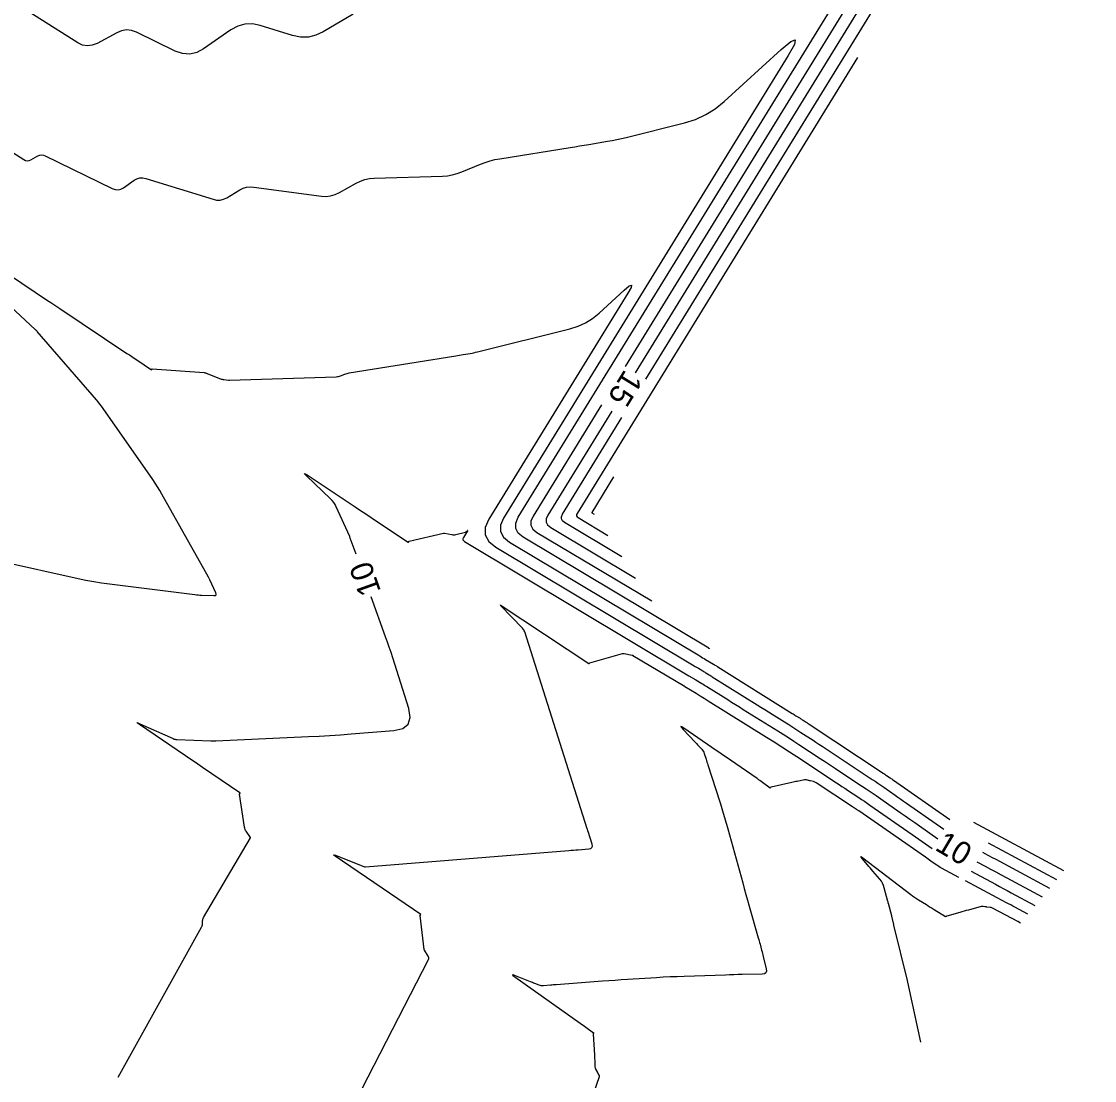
# Model space of a CAD drawing. Extents: x 1797789 to 1803805, y 249066 to 250293.
# Drawn here: x 1798416.4 to 1798702, y 249648.7 to 249930.5 of the extents above; entities that cross this region are included whole.
import ezdxf

# ---------------------------------------------------------------- set-up
doc = ezdxf.new("R2010")
doc.units = 0
doc.layers.add('33', color=7, linetype='Continuous')
doc.layers.add('34', color=7, linetype='Continuous')

msp = doc.modelspace()

# ---------------------------------------------------------------- linework, layer by layer
at = {"layer": '33'}
for points in [[(1798699.28, 250031.22), (1798579.8, 249837.04)], [(1798573.51, 249826.82), (1798556.48, 249799.14), (1798556.07, 249798.17), (1798556.06, 249797.31), (1798556.46, 249796.55), (1798557.28, 249795.89), (1798579.84, 249782.4)], [(1798505.48, 249788.76), (1798503.94, 249793.08), (1798503.9, 249793.17), (1798503.86, 249793.27), (1798503.82, 249793.37), (1798503.78, 249793.46), (1798500.21, 249801.39), (1798499.91, 249801.97), (1798499.56, 249802.52), (1798499.16, 249803.03), (1798498.71, 249803.5), (1798492.25, 249809.64), (1798491.81, 249810.08), (1798491.7, 249810.27), (1798491.9, 249810.19), (1798492.43, 249809.86), (1798505.2, 249801.37), (1798506.62, 249800.43), (1798508.04, 249799.49), (1798509.46, 249798.54), (1798510.88, 249797.6), (1798519.38, 249791.96), (1798519.39, 249791.96), (1798519.41, 249791.95), (1798519.42, 249791.96), (1798519.43, 249791.97), (1798519.59, 249792.21), (1798519.59, 249792.22), (1798519.6, 249792.21), (1798519.6, 249792.21), (1798528.76, 249794.39), (1798528.82, 249794.4), (1798528.88, 249794.41), (1798528.93, 249794.4), (1798528.99, 249794.39), (1798530.94, 249793.99), (1798531.21, 249793.95), (1798531.48, 249793.94), (1798531.75, 249793.96), (1798532.01, 249794.01), (1798534.57, 249794.65), (1798534.65, 249794.67), (1798534.73, 249794.71), (1798534.8, 249794.75), (1798534.86, 249794.8), (1798535.11, 249795.03), (1798535.16, 249795.08), (1798535.19, 249795.08), (1798535.18, 249795.06), (1798535.15, 249795), (1798534.05, 249793.21), (1798533.91, 249792.9), (1798533.91, 249792.63), (1798534.04, 249792.39), (1798534.3, 249792.18), (1798594.06, 249756.45), (1798594.22, 249756.36), (1798594.37, 249756.27), (1798594.52, 249756.18), (1798594.67, 249756.09), (1798595.27, 249755.72), (1798595.42, 249755.63), (1798595.57, 249755.54), (1798595.72, 249755.45), (1798595.87, 249755.36), (1798597.53, 249754.35), (1798597.86, 249754.16), (1798598.19, 249753.96), (1798598.51, 249753.76), (1798598.84, 249753.55), (1798604.39, 249750.09), (1798605.42, 249749.44), (1798606.45, 249748.79), (1798607.49, 249748.15), (1798608.52, 249747.5), (1798617.71, 249741.77), (1798619.13, 249740.88), (1798620.54, 249739.98), (1798621.95, 249739.07), (1798623.35, 249738.15), (1798629.03, 249734.4), (1798630.39, 249733.51), (1798631.74, 249732.61), (1798633.1, 249731.72), (1798634.45, 249730.83), (1798639.97, 249727.18), (1798641.27, 249726.32), (1798642.57, 249725.44), (1798643.86, 249724.56), (1798645.15, 249723.67), (1798650.3, 249720.09), (1798651.58, 249719.2), (1798652.87, 249718.3), (1798654.15, 249717.41), (1798655.44, 249716.51), (1798660.35, 249713.08)], [(1798442.18, 249649.63), (1798464.36, 249689.51), (1798464.46, 249689.71), (1798464.53, 249689.92), (1798464.58, 249690.13), (1798464.6, 249690.36), (1798464.63, 249691.25), (1798464.66, 249691.48), (1798464.7, 249691.69), (1798464.78, 249691.89), (1798464.88, 249692.09), (1798477.37, 249713.28), (1798477.39, 249713.31), (1798477.39, 249713.34), (1798477.39, 249713.37), (1798477.37, 249713.4), (1798476.25, 249715.05), (1798476.1, 249715.31), (1798475.98, 249715.57), (1798475.89, 249715.85), (1798475.83, 249716.13), (1798474.45, 249724.96), (1798474.45, 249724.97), (1798474.44, 249724.97), (1798474.45, 249724.97), (1798474.6, 249725.21), (1798474.61, 249725.23), (1798474.61, 249725.24), (1798474.61, 249725.26), (1798474.59, 249725.27), (1798464.61, 249732.05), (1798463.97, 249732.48), (1798463.34, 249732.91), (1798462.71, 249733.34), (1798462.08, 249733.77), (1798447.83, 249743.43), (1798447.32, 249743.8), (1798447.18, 249743.96), (1798447.39, 249743.92), (1798447.97, 249743.68), (1798456.82, 249739.71), (1798457.06, 249739.61), (1798457.31, 249739.54), (1798457.56, 249739.49), (1798457.82, 249739.47), (1798466.86, 249739.15), (1798467.18, 249739.14), (1798467.51, 249739.14), (1798467.84, 249739.15), (1798468.17, 249739.16), (1798492.86, 249740.25), (1798495.7, 249740.39), (1798498.54, 249740.55), (1798501.38, 249740.74), (1798504.22, 249740.96), (1798515.56, 249741.88), (1798517.93, 249742.42), (1798519.38, 249743.58), (1798519.91, 249745.36), (1798519.51, 249747.76), (1798515.23, 249761.23), (1798514.78, 249762.63), (1798514.32, 249764.02), (1798513.84, 249765.41), (1798513.35, 249766.79), (1798509.53, 249777.46)], [(1798670.67, 249706.95), (1798672.89, 249705.77), (1798674.33, 249705), (1798675.76, 249704.24), (1798677.2, 249703.47), (1798678.63, 249702.7), (1798688.06, 249697.65)]]:
    msp.add_lwpolyline(points, dxfattribs=at)
at = {"layer": '34'}
for points in [[(1798696.56, 250032.9), (1798577.08, 249838.71)], [(1798702.01, 250029.55), (1798582.53, 249835.36)], [(1798599.67, 249763.57), (1798599.4, 249763.73), (1798599.37, 249763.75), (1798549.96, 249793.28), (1798548.62, 249794.37), (1798547.96, 249795.63), (1798547.97, 249797.04), (1798548.66, 249798.63), (1798663.16, 249984.74)], [(1798504.7, 249932.46), (1798496.77, 249927.75), (1798494.81, 249926.83), (1798492.8, 249926.36), (1798490.73, 249926.35), (1798488.61, 249926.79), (1798479.95, 249929.48), (1798477.89, 249929.89), (1798475.89, 249929.83), (1798473.98, 249929.29), (1798472.13, 249928.27), (1798464.9, 249923.24), (1798463.07, 249922.26), (1798461.2, 249921.84), (1798459.28, 249921.97), (1798457.32, 249922.66), (1798447.08, 249927.65), (1798445.75, 249928.13), (1798444.42, 249928.27), (1798443.1, 249928.07), (1798441.79, 249927.53), (1798436.56, 249924.69), (1798435.26, 249924.17), (1798433.97, 249924.02), (1798432.69, 249924.25), (1798431.43, 249924.86), (1798418.65, 249932.91)], [(1798398.94, 249905.2), (1798417.08, 249893.76), (1798417.54, 249893.54), (1798418, 249893.46), (1798418.46, 249893.51), (1798418.93, 249893.7), (1798420.83, 249894.73), (1798421.3, 249894.93), (1798421.78, 249895), (1798422.26, 249894.95), (1798422.74, 249894.77), (1798440.6, 249886.06), (1798441.37, 249885.79), (1798442.13, 249885.74), (1798442.87, 249885.91), (1798443.59, 249886.29), (1798446.45, 249888.28), (1798447.17, 249888.68), (1798447.93, 249888.89), (1798448.72, 249888.92), (1798449.53, 249888.75), (1798467.41, 249883.2), (1798468.36, 249883), (1798469.29, 249883.01), (1798470.19, 249883.22), (1798471.07, 249883.63), (1798474.54, 249885.69), (1798475.42, 249886.13), (1798476.34, 249886.4), (1798477.29, 249886.51), (1798478.27, 249886.45), (1798496.25, 249884.05), (1798497.51, 249883.98), (1798498.72, 249884.11), (1798499.9, 249884.44), (1798501.04, 249884.97), (1798505.51, 249887.49), (1798506.65, 249888.05), (1798507.83, 249888.46), (1798509.06, 249888.72), (1798510.32, 249888.83), (1798528.45, 249889.39), (1798529.78, 249889.49), (1798531.09, 249889.71), (1798532.37, 249890.05), (1798533.63, 249890.5), (1798538.61, 249892.55), (1798539.86, 249893.02), (1798541.14, 249893.42), (1798542.44, 249893.75), (1798543.76, 249894), (1798562.5, 249897), (1798563.74, 249897.2), (1798564.98, 249897.4), (1798566.22, 249897.61), (1798567.46, 249897.81), (1798572.41, 249898.64), (1798573.65, 249898.86), (1798574.88, 249899.1), (1798576.11, 249899.37), (1798577.33, 249899.66), (1798592.89, 249903.56), (1798595.8, 249904.47), (1798598.53, 249905.73), (1798601.08, 249907.31), (1798603.45, 249909.23), (1798618.59, 249923.07), (1798621.17, 249925.22), (1798622.35, 249925.67), (1798622.12, 249924.43), (1798620.49, 249921.49), (1798544.74, 249798.38), (1798543.92, 249796.48), (1798543.91, 249794.78), (1798544.7, 249793.28), (1798546.31, 249791.98), (1798596.94, 249761.71), (1798597.32, 249761.48), (1798597.71, 249761.25), (1798598.1, 249761.02), (1798598.48, 249760.78), (1798600.6, 249759.5), (1798600.7, 249759.44), (1798600.79, 249759.39), (1798600.89, 249759.33), (1798600.98, 249759.27), (1798601.36, 249759.04), (1798601.46, 249758.98), (1798601.55, 249758.93), (1798601.65, 249758.87), (1798601.74, 249758.81), (1798621.55, 249746.43), (1798621.8, 249746.28), (1798622.05, 249746.12), (1798622.29, 249745.97), (1798622.54, 249745.81), (1798623.64, 249745.13), (1798623.84, 249745), (1798624.04, 249744.87), (1798624.24, 249744.75), (1798624.43, 249744.62), (1798625.23, 249744.09), (1798625.42, 249743.96), (1798625.62, 249743.83), (1798625.82, 249743.7), (1798626.02, 249743.57), (1798645.72, 249730.56), (1798645.96, 249730.41), (1798646.19, 249730.25), (1798646.42, 249730.09), (1798646.65, 249729.93), (1798647.58, 249729.29), (1798647.81, 249729.13), (1798648.04, 249728.97), (1798648.27, 249728.8), (1798648.5, 249728.64), (1798663.47, 249718.21)], [(1798638.95, 249920.96), (1798564.31, 249799.64), (1798564.16, 249799.3), (1798564.16, 249799), (1798564.3, 249798.73), (1798564.59, 249798.5), (1798572.52, 249793.76)], [(1798406.36, 249867.73), (1798423.4, 249856.32), (1798424.21, 249855.78), (1798425.02, 249855.23), (1798425.83, 249854.69), (1798426.64, 249854.15), (1798444.5, 249842.21), (1798445.15, 249841.78), (1798445.8, 249841.34), (1798446.46, 249840.9), (1798447.11, 249840.47), (1798451.02, 249837.86), (1798451.03, 249837.85), (1798451.04, 249837.85), (1798451.05, 249837.86), (1798451.05, 249837.86), (1798451.22, 249838.12), (1798451.22, 249838.12), (1798451.23, 249838.12), (1798451.24, 249838.11), (1798451.24, 249838.11), (1798465.1, 249837.09), (1798465.22, 249837.07), (1798465.35, 249837.05), (1798465.47, 249837.01), (1798465.59, 249836.97), (1798469.38, 249835.45), (1798469.59, 249835.38), (1798469.81, 249835.31), (1798470.03, 249835.26), (1798470.25, 249835.22), (1798471.57, 249835.05), (1798471.59, 249835.05), (1798471.61, 249835.05), (1798471.62, 249835.05), (1798471.64, 249835.06), (1798471.71, 249835.1), (1798471.72, 249835.11), (1798471.74, 249835.11), (1798471.76, 249835.11), (1798471.77, 249835.12), (1798500.21, 249835.99), (1798500.51, 249836.02), (1798500.81, 249836.06), (1798501.1, 249836.14), (1798501.38, 249836.24), (1798502.51, 249836.71), (1798502.79, 249836.81), (1798503.08, 249836.9), (1798503.38, 249836.98), (1798503.67, 249837.03), (1798532.03, 249841.58), (1798532.51, 249841.66), (1798532.99, 249841.73), (1798533.47, 249841.81), (1798533.95, 249841.89), (1798535.87, 249842.21), (1798536.35, 249842.3), (1798536.83, 249842.39), (1798537.31, 249842.5), (1798537.78, 249842.61), (1798562.41, 249848.77), (1798564.55, 249849.45), (1798566.55, 249850.36), (1798568.42, 249851.53), (1798570.16, 249852.93), (1798576.85, 249859.05), (1798578.17, 249860.15), (1798578.77, 249860.38), (1798578.65, 249859.75), (1798577.82, 249858.25), (1798540.83, 249798.12), (1798539.87, 249795.91), (1798539.85, 249793.94), (1798540.78, 249792.19), (1798542.65, 249790.67), (1798595.5, 249759.08), (1798595.77, 249758.92), (1798596.04, 249758.76), (1798596.31, 249758.6), (1798596.57, 249758.44), (1798597.76, 249757.72), (1798597.97, 249757.59), (1798598.18, 249757.46), (1798598.39, 249757.34), (1798598.6, 249757.21), (1798599.45, 249756.7), (1798599.66, 249756.57), (1798599.87, 249756.44), (1798600.08, 249756.31), (1798600.29, 249756.18), (1798612.24, 249748.71), (1798613.24, 249748.09), (1798614.25, 249747.46), (1798615.26, 249746.83), (1798616.26, 249746.2), (1798620.67, 249743.45), (1798621.48, 249742.94), (1798622.29, 249742.43), (1798623.09, 249741.91), (1798623.89, 249741.38), (1798627.09, 249739.28), (1798627.88, 249738.75), (1798628.68, 249738.22), (1798629.48, 249737.7), (1798630.28, 249737.17), (1798642.84, 249728.87), (1798643.61, 249728.36), (1798644.38, 249727.85), (1798645.14, 249727.32), (1798645.9, 249726.8), (1798648.94, 249724.69), (1798649.69, 249724.16), (1798650.45, 249723.63), (1798651.21, 249723.11), (1798651.97, 249722.58), (1798661.89, 249715.66)], [(1798410.89, 249786.95), (1798431.54, 249782.3), (1798433.6, 249781.87), (1798435.67, 249781.48), (1798437.75, 249781.14), (1798439.84, 249780.86), (1798462.57, 249778.02), (1798463.01, 249777.97), (1798463.44, 249777.93), (1798463.88, 249777.9), (1798464.32, 249777.88), (1798467.64, 249777.76), (1798468, 249777.8), (1798468.21, 249777.94), (1798468.26, 249778.18), (1798468.16, 249778.53), (1798466.59, 249782), (1798466.51, 249782.18), (1798466.42, 249782.35), (1798466.33, 249782.53), (1798466.23, 249782.7), (1798453.83, 249804.76), (1798453.25, 249805.76), (1798452.65, 249806.73), (1798452.03, 249807.7), (1798451.39, 249808.65), (1798438.17, 249827.58), (1798437.75, 249828.16), (1798437.32, 249828.73), (1798436.88, 249829.29), (1798436.41, 249829.83), (1798420.62, 249848.04), (1798420.5, 249848.18), (1798420.37, 249848.31), (1798420.24, 249848.45), (1798420.11, 249848.57), (1798402.76, 249864.58)], [(1798570.79, 249828.49), (1798552.57, 249798.88), (1798552.02, 249797.61), (1798552.01, 249796.47), (1798552.54, 249795.46), (1798553.62, 249794.59), (1798584.15, 249776.34)], [(1798576.18, 249788.08), (1798560.93, 249797.2), (1798560.38, 249797.64), (1798560.11, 249798.16), (1798560.11, 249798.74), (1798560.4, 249799.39), (1798576.24, 249825.14)], [(1798574.03, 249809.33), (1798568.22, 249799.9), (1798568.21, 249799.87), (1798568.21, 249799.85), (1798568.22, 249799.83), (1798568.25, 249799.81), (1798568.86, 249799.44)], [(1798475.1, 249584.37), (1798524.74, 249680.93), (1798524.83, 249681.16), (1798524.85, 249681.4), (1798524.8, 249681.63), (1798524.69, 249681.85), (1798523.69, 249683.43), (1798523.67, 249683.47), (1798523.65, 249683.51), (1798523.64, 249683.55), (1798523.63, 249683.59), (1798522.56, 249692.66), (1798522.56, 249692.67), (1798522.56, 249692.67), (1798522.74, 249692.93), (1798522.74, 249692.94), (1798522.74, 249692.94), (1798522.74, 249692.94), (1798522.73, 249692.95), (1798499.89, 249708.48), (1798499.61, 249708.69), (1798499.53, 249708.79), (1798499.66, 249708.78), (1798499.99, 249708.66), (1798507.69, 249705.62), (1798507.76, 249705.6), (1798507.83, 249705.58), (1798507.9, 249705.58), (1798507.98, 249705.58), (1798562.09, 249709.96), (1798562.72, 249710.01), (1798563.34, 249710.06), (1798563.97, 249710.11), (1798564.6, 249710.16), (1798567.44, 249710.39), (1798567.95, 249710.51), (1798568.26, 249710.75), (1798568.37, 249711.13), (1798568.29, 249711.64), (1798567.24, 249714.99), (1798567.22, 249715.05), (1798567.2, 249715.11), (1798567.18, 249715.17), (1798567.16, 249715.23), (1798567.08, 249715.46), (1798567.06, 249715.52), (1798567.04, 249715.58), (1798567.03, 249715.63), (1798567.01, 249715.69), (1798550.36, 249768.13), (1798550.26, 249768.39), (1798550.14, 249768.63), (1798549.99, 249768.86), (1798549.81, 249769.07), (1798544.05, 249775.07), (1798543.93, 249775.21), (1798543.9, 249775.27), (1798543.96, 249775.25), (1798544.12, 249775.16), (1798567.46, 249759.68), (1798567.49, 249759.66), (1798567.52, 249759.66), (1798567.54, 249759.67), (1798567.56, 249759.7), (1798567.71, 249759.91), (1798567.71, 249759.91), (1798567.72, 249759.91), (1798576.38, 249762.32), (1798576.49, 249762.34), (1798576.6, 249762.35), (1798576.71, 249762.35), (1798576.82, 249762.34), (1798578.92, 249761.96), (1798578.99, 249761.94), (1798579.05, 249761.92), (1798579.11, 249761.9), (1798579.17, 249761.87), (1798592.63, 249753.82), (1798592.66, 249753.8), (1798592.69, 249753.78), (1798592.73, 249753.76), (1798592.76, 249753.74), (1798592.92, 249753.64), (1798593.02, 249753.58), (1798595.96, 249751.8), (1798596.23, 249751.64), (1798596.51, 249751.47), (1798596.78, 249751.31), (1798597.04, 249751.14), (1798598.12, 249750.47), (1798598.39, 249750.3), (1798598.66, 249750.13), (1798598.93, 249749.96), (1798599.2, 249749.79), (1798614.74, 249740.09), (1798616.77, 249738.82), (1798618.79, 249737.53), (1798620.8, 249736.23), (1798622.81, 249734.92), (1798633.31, 249727.99), (1798634.06, 249727.5), (1798634.8, 249727.01), (1798635.55, 249726.51), (1798636.3, 249726.02), (1798639.28, 249724.05), (1798640.03, 249723.55), (1798640.77, 249723.05), (1798641.51, 249722.55), (1798642.25, 249722.04), (1798653.5, 249714.21), (1798654.39, 249713.59), (1798655.28, 249712.97), (1798656.17, 249712.35), (1798657.06, 249711.73), (1798658.82, 249710.5)], [(1798665.93, 249702.78), (1798661.31, 249705.25), (1798660.93, 249705.46), (1798660.55, 249705.68), (1798660.19, 249705.91), (1798659.83, 249706.15), (1798658.41, 249707.14), (1798658.05, 249707.39), (1798657.69, 249707.64), (1798657.34, 249707.88), (1798656.98, 249708.13), (1798639.24, 249720.48), (1798639.11, 249720.57), (1798638.97, 249720.66), (1798638.83, 249720.76), (1798638.7, 249720.85), (1798638.14, 249721.21), (1798638, 249721.31), (1798637.87, 249721.4), (1798637.73, 249721.49), (1798637.59, 249721.58), (1798627.89, 249727.97), (1798627.73, 249728.07), (1798627.57, 249728.15), (1798627.4, 249728.21), (1798627.22, 249728.26), (1798626.42, 249728.46), (1798626.28, 249728.49), (1798626.15, 249728.52), (1798626.01, 249728.55), (1798625.87, 249728.59), (1798625.33, 249728.72), (1798625.2, 249728.75), (1798625.06, 249728.76), (1798624.92, 249728.75), (1798624.79, 249728.73), (1798622.88, 249728.34), (1798622.51, 249728.27), (1798622.15, 249728.19), (1798621.79, 249728.12), (1798621.43, 249728.04), (1798615.91, 249726.82), (1798615.9, 249726.82), (1798615.9, 249726.83), (1798615.74, 249726.61), (1798615.73, 249726.59), (1798615.71, 249726.57), (1798615.71, 249726.56), (1798615.7, 249726.56), (1798615.7, 249726.56), (1798615.69, 249726.56), (1798613.67, 249728.03), (1798612.94, 249728.56), (1798612.75, 249728.7), (1798612.57, 249728.83), (1798612.38, 249728.96), (1798612.2, 249729.09), (1798605.12, 249733.96), (1798602.63, 249735.66), (1798600.15, 249737.37), (1798592.74, 249742.47), (1798592.18, 249742.82), (1798591.95, 249742.9), (1798592.06, 249742.68), (1798592.5, 249742.18), (1798595.69, 249738.79), (1798595.92, 249738.55), (1798596.14, 249738.31), (1798596.37, 249738.07), (1798596.59, 249737.83), (1798597.5, 249736.87), (1798597.71, 249736.62), (1798597.88, 249736.36), (1798598.03, 249736.07), (1798598.14, 249735.77), (1798598.63, 249734.22), (1798598.74, 249733.85), (1798598.86, 249733.49), (1798598.98, 249733.13), (1798599.09, 249732.77), (1798602.26, 249722.91), (1798602.45, 249722.32), (1798602.64, 249721.72), (1798602.82, 249721.12), (1798603, 249720.52), (1798603.71, 249718.12), (1798603.88, 249717.52), (1798604.05, 249716.92), (1798604.22, 249716.32), (1798604.39, 249715.72), (1798608.37, 249701.38), (1798608.8, 249699.83), (1798609.23, 249698.27), (1798609.67, 249696.72), (1798610.11, 249695.17), (1798612.53, 249686.69), (1798612.64, 249686.27), (1798612.76, 249685.86), (1798612.87, 249685.45), (1798612.98, 249685.04), (1798613.42, 249683.39), (1798613.53, 249682.97), (1798613.64, 249682.56), (1798613.74, 249682.15), (1798613.84, 249681.73), (1798614.63, 249678.44), (1798614.69, 249677.84), (1798614.53, 249677.4), (1798614.15, 249677.14), (1798613.55, 249677.04), (1798608.25, 249676.94), (1798607.13, 249676.91), (1798606.01, 249676.89), (1798604.89, 249676.86), (1798603.77, 249676.82), (1798592.76, 249676.44), (1798590.92, 249676.37), (1798589.09, 249676.29), (1798587.25, 249676.2), (1798585.41, 249676.09), (1798577.75, 249675.62), (1798576.07, 249675.52), (1798574.4, 249675.4), (1798572.72, 249675.29), (1798571.05, 249675.16), (1798558.74, 249674.23), (1798558.36, 249674.2), (1798557.98, 249674.17), (1798557.61, 249674.13), (1798557.23, 249674.1), (1798555.35, 249673.93), (1798555.05, 249673.93), (1798554.75, 249673.95), (1798554.45, 249674.01), (1798554.17, 249674.11), (1798553.02, 249674.57), (1798552.74, 249674.69), (1798552.45, 249674.81), (1798552.17, 249674.92), (1798551.88, 249675.04), (1798547.91, 249676.64), (1798547.33, 249676.85), (1798547.11, 249676.86), (1798547.24, 249676.68), (1798547.73, 249676.31), (1798565.16, 249664.02), (1798565.52, 249663.76), (1798565.88, 249663.5), (1798566.24, 249663.24), (1798566.6, 249662.98), (1798568.7, 249661.42), (1798568.72, 249661.4), (1798568.73, 249661.37), (1798568.73, 249661.35), (1798568.71, 249661.32), (1798568.6, 249661.16), (1798568.59, 249661.14), (1798568.56, 249661.11), (1798568.56, 249661.11), (1798568.56, 249661.1), (1798568.91, 249655.56), (1798568.93, 249655.21), (1798568.95, 249654.86), (1798568.97, 249654.51), (1798568.99, 249654.15), (1798569.06, 249652.38), (1798569.08, 249652.21), (1798569.12, 249652.05), (1798569.17, 249651.9), (1798569.24, 249651.75), (1798569.61, 249651.1), (1798569.67, 249650.98), (1798569.73, 249650.87), (1798569.8, 249650.75), (1798569.86, 249650.64), (1798570.12, 249650.18), (1798570.17, 249650.06), (1798570.19, 249649.94), (1798570.19, 249649.82), (1798570.16, 249649.7), (1798557.48, 249613.27)], [(1798693.83, 249704.55), (1798669.86, 249717.41), (1798669.86, 249717.41), (1798669.85, 249717.42)], [(1798673.68, 249712.02), (1798691.9, 249702.25)], [(1798655.78, 249658.97), (1798653.68, 249668.79), (1798653.33, 249670.43), (1798652.96, 249672.06), (1798652.59, 249673.69), (1798652.2, 249675.32), (1798648.63, 249690.11), (1798648.58, 249690.31), (1798648.53, 249690.52), (1798648.49, 249690.72), (1798648.44, 249690.92), (1798648.24, 249691.73), (1798648.19, 249691.93), (1798648.14, 249692.13), (1798648.09, 249692.34), (1798648.04, 249692.54), (1798647.16, 249695.82), (1798647.12, 249695.97), (1798647.08, 249696.11), (1798647.05, 249696.25), (1798647.01, 249696.39), (1798646.06, 249700.04), (1798645.86, 249700.66), (1798645.6, 249701.24), (1798645.27, 249701.79), (1798644.88, 249702.31), (1798643.04, 249704.46), (1798642.68, 249704.89), (1798642.32, 249705.31), (1798641.96, 249705.73), (1798641.6, 249706.16), (1798640.16, 249707.85), (1798639.9, 249708.18), (1798639.84, 249708.32), (1798639.98, 249708.27), (1798640.32, 249708.02), (1798653.1, 249698.26), (1798653.6, 249697.89), (1798654.1, 249697.54), (1798654.61, 249697.19), (1798655.13, 249696.86), (1798657.25, 249695.54), (1798657.77, 249695.22), (1798658.29, 249694.9), (1798658.8, 249694.58), (1798659.32, 249694.26), (1798662.39, 249692.35), (1798662.41, 249692.34), (1798662.43, 249692.34), (1798662.45, 249692.35), (1798662.46, 249692.36), (1798662.54, 249692.46), (1798662.55, 249692.47), (1798662.56, 249692.48), (1798662.57, 249692.5), (1798662.58, 249692.51), (1798662.64, 249692.58), (1798662.64, 249692.58), (1798662.65, 249692.58), (1798662.73, 249692.57), (1798662.74, 249692.56), (1798662.76, 249692.56), (1798662.77, 249692.57), (1798662.79, 249692.57), (1798666.23, 249693.56), (1798666.81, 249693.72), (1798667.39, 249693.88), (1798667.97, 249694.04), (1798668.55, 249694.2), (1798671.93, 249695.1), (1798672.04, 249695.12), (1798672.15, 249695.13), (1798672.27, 249695.14), (1798672.38, 249695.13), (1798672.84, 249695.07), (1798672.96, 249695.05), (1798673.07, 249695.03), (1798673.19, 249695.02), (1798673.3, 249695), (1798674.23, 249694.88), (1798674.42, 249694.84), (1798674.6, 249694.79), (1798674.78, 249694.72), (1798674.96, 249694.64), (1798681.51, 249691.16), (1798681.59, 249691.11), (1798681.67, 249691.07), (1798681.74, 249691.03), (1798681.82, 249690.99), (1798682.29, 249690.74)], [(1798672.18, 249709.49), (1798672.84, 249709.14), (1798673.8, 249708.63), (1798674.75, 249708.11), (1798675.71, 249707.6), (1798689.98, 249699.95)], [(1798669.16, 249704.41), (1798675.63, 249700.97), (1798676.68, 249700.41), (1798677.73, 249699.85), (1798678.78, 249699.29), (1798679.83, 249698.72), (1798686.14, 249695.34)], [(1798684.22, 249693.04), (1798680.83, 249694.86), (1798680.26, 249695.16), (1798679.7, 249695.46), (1798679.13, 249695.76), (1798678.57, 249696.06), (1798667.65, 249701.87)]]:
    msp.add_lwpolyline(points, dxfattribs=at)

# ---------------------------------------------------------------- texts
at = {"layer": '33'}
for s, rotation, p in [('15', 238.3964, (1798576.98, 249838.18)), ('10', 109.7143, (1798512.19, 249778.94)), ('10', 329.263, (1798659.25, 249710.25))]:
    msp.add_text(s, height=6, rotation=rotation, dxfattribs=at).set_placement(p)

doc.saveas('drawing.dxf')
